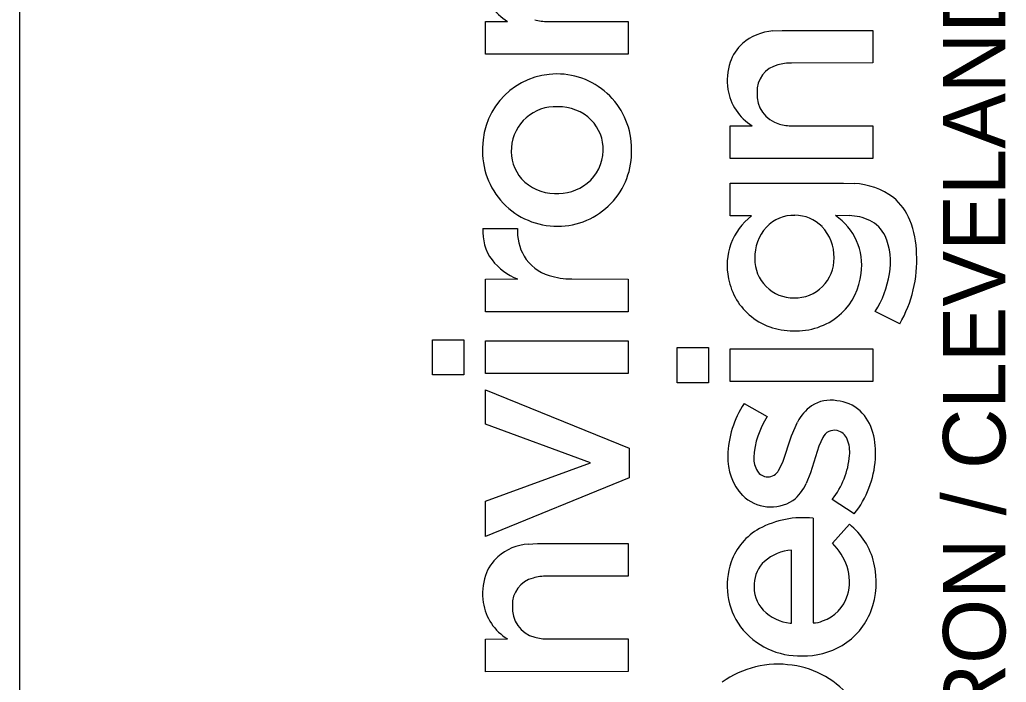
# Model space of a CAD drawing. Extents: x -0.2 to 34, y 0 to 22.
# Drawn here: x 32 to 32.901, y 2.778 to 3.382 of the extents above; entities that cross this region are included whole.
import ezdxf

# ---------------------------------------------------------------- set-up
doc = ezdxf.new("R2010")
doc.units = 0
doc.layers.add('SG_P_Poles', color=7, linetype='Continuous')
doc.layers.add('SH_Data', color=7, linetype='Continuous')

msp = doc.modelspace()

# ---------------------------------------------------------------- linework, layer by layer
at = {"layer": 'SG_P_Poles'}
msp.add_line((32, 0.5), (32, 21.5), dxfattribs=at)
at = {"layer": 'SH_Data'}
for p, q in [((32.42542, 3.38066), (32.44552, 3.38071)), ((32.42542, 3.35086), (32.42542, 3.38066)), ((32.48222, 3.38071), (32.55569, 3.38071)), ((32.55569, 3.38071), (32.55571, 3.35096)), ((32.68784, 3.3722), (32.69634, 3.37266)), ((32.69634, 3.37266), (32.77916, 3.37266)), ((32.77916, 3.37266), (32.77917, 3.34287)), ((32.55571, 3.35096), (32.42542, 3.35086)), ((32.77917, 3.34287), (32.70485, 3.3428)), ((32.64888, 3.2855), (32.66897, 3.28555)), ((32.64888, 3.25569), (32.64888, 3.2855)), ((32.70568, 3.28555), (32.77915, 3.28555)), ((32.77915, 3.28555), (32.77917, 3.25579)), ((32.77917, 3.25579), (32.64888, 3.25569)), ((32.6489, 3.20336), (32.64889, 3.23322)), ((32.64889, 3.23322), (32.75236, 3.23322)), ((32.75236, 3.23322), (32.76191, 3.23285)), ((32.66836, 3.20336), (32.6489, 3.20336)), ((32.75763, 3.20356), (32.74487, 3.20361)), ((32.42299, 3.19193), (32.45454, 3.19193)), ((32.42542, 3.14577), (32.45473, 3.14579)), ((32.42542, 3.11593), (32.42542, 3.14577)), ((32.50413, 3.14581), (32.55571, 3.14573)), ((32.55571, 3.14573), (32.55565, 3.11593)), ((32.55565, 3.11593), (32.42542, 3.11593)), ((32.8036, 3.10491), (32.7812, 3.11598)), ((32.37705, 3.05818), (32.37705, 3.09026)), ((32.37705, 3.09026), (32.40543, 3.09026)), ((32.40543, 3.09026), (32.40543, 3.05818)), ((32.42542, 3.05942), (32.42542, 3.08928)), ((32.42542, 3.08928), (32.55571, 3.08928)), ((32.55571, 3.08928), (32.55571, 3.05942)), ((32.60051, 3.05111), (32.60051, 3.08319)), ((32.60051, 3.08319), (32.62889, 3.08319)), ((32.62889, 3.08319), (32.62889, 3.05111)), ((32.64888, 3.05234), (32.64888, 3.0822)), ((32.64888, 3.0822), (32.77917, 3.0822)), ((32.77917, 3.0822), (32.77917, 3.05234)), ((32.40543, 3.05818), (32.37705, 3.05818)), ((32.55571, 3.05942), (32.42542, 3.05942)), ((32.62889, 3.05111), (32.60051, 3.05111)), ((32.77917, 3.05234), (32.64888, 3.05234)), ((32.42542, 3.01327), (32.42542, 3.0446)), ((32.42542, 3.0446), (32.5567, 2.9913)), ((32.66151, 3.03207), (32.68268, 3.02025)), ((32.52117, 2.97798), (32.42542, 3.01327)), ((32.70483, 3.00258), (32.71036, 3.01526)), ((32.69675, 2.97868), (32.70483, 3.00258)), ((32.73342, 3.00101), (32.72985, 2.9933)), ((32.5567, 2.9913), (32.5567, 2.96441)), ((32.72985, 2.9933), (32.72213, 2.96882)), ((32.42542, 2.94294), (32.52117, 2.97798)), ((32.69299, 2.97117), (32.69675, 2.97868)), ((32.5567, 2.96441), (32.42542, 2.91086)), ((32.72213, 2.96882), (32.71822, 2.95921)), ((32.42542, 2.91086), (32.42542, 2.94294)), ((32.76214, 2.93141), (32.74198, 2.94469)), ((32.72453, 2.92747), (32.72463, 2.83195)), ((32.74228, 2.90465), (32.75768, 2.922)), ((32.46439, 2.90397), (32.47289, 2.90443)), ((32.47289, 2.90443), (32.55571, 2.90443)), ((32.55571, 2.90443), (32.55571, 2.87465)), ((32.70489, 2.83182), (32.70489, 2.89834)), ((32.55571, 2.87465), (32.4814, 2.87457)), ((32.70361, 2.83165), (32.70489, 2.83182)), ((32.42542, 2.81728), (32.44552, 2.81733)), ((32.42542, 2.78747), (32.42542, 2.81728)), ((32.48222, 2.81733), (32.55569, 2.81733)), ((32.55569, 2.81733), (32.55571, 2.78756)), ((32.55571, 2.78756), (32.42542, 2.78747))]:
    msp.add_line(p, q, dxfattribs=at)
for points in [[(32.42542, 3.35086), (32.42542, 3.38066), (32.44552, 3.38071)], [(32.48222, 3.38071), (32.55569, 3.38071), (32.55571, 3.35096), (32.42542, 3.35086)], [(32.68784, 3.3722), (32.69634, 3.37266), (32.77916, 3.37266), (32.77917, 3.34287), (32.70485, 3.3428)], [(32.64888, 3.25569), (32.64888, 3.2855), (32.66897, 3.28555)], [(32.70568, 3.28555), (32.77915, 3.28555), (32.77917, 3.25579), (32.64888, 3.25569)], [(32.66836, 3.20336), (32.6489, 3.20336), (32.64889, 3.23322), (32.75236, 3.23322), (32.76191, 3.23285)], [(32.75763, 3.20356), (32.74487, 3.20361)], [(32.42299, 3.19193), (32.45454, 3.19193)], [(32.50413, 3.14581), (32.55571, 3.14573), (32.55565, 3.11593), (32.42542, 3.11593)], [(32.42542, 3.11593), (32.42542, 3.14577), (32.45473, 3.14579)], [(32.8036, 3.10491), (32.7812, 3.11598)], [(32.66151, 3.03207), (32.68268, 3.02025)], [(32.69299, 2.97117), (32.69675, 2.97868), (32.70483, 3.00258), (32.71036, 3.01526)], [(32.73342, 3.00101), (32.72985, 2.9933), (32.72213, 2.96882), (32.71822, 2.95921)], [(32.76214, 2.93141), (32.74198, 2.94469)], [(32.72453, 2.92747), (32.72463, 2.83195)], [(32.74228, 2.90465), (32.75768, 2.922)], [(32.46439, 2.90397), (32.47289, 2.90443), (32.55571, 2.90443), (32.55571, 2.87465), (32.4814, 2.87457)], [(32.70361, 2.83165), (32.70489, 2.83182), (32.70489, 2.89834)], [(32.42542, 2.78747), (32.42542, 2.81728), (32.44552, 2.81733)], [(32.48222, 2.81733), (32.55569, 2.81733), (32.55571, 2.78756), (32.42542, 2.78747)]]:
    msp.add_lwpolyline(points, dxfattribs=at)
for points in [[(32.37705, 3.05818), (32.37705, 3.09026), (32.40543, 3.09026), (32.40543, 3.05818)], [(32.42542, 3.05942), (32.42542, 3.08928), (32.55571, 3.08928), (32.55571, 3.05942)], [(32.60051, 3.05111), (32.60051, 3.08319), (32.62889, 3.08319), (32.62889, 3.05111)], [(32.64888, 3.05234), (32.64888, 3.0822), (32.77917, 3.0822), (32.77917, 3.05234)], [(32.42542, 2.91086), (32.42542, 2.94294), (32.52117, 2.97798), (32.42542, 3.01327), (32.42542, 3.0446), (32.5567, 2.9913), (32.5567, 2.96441)]]:
    msp.add_lwpolyline(points, close=True, dxfattribs=at)
for centre, radius, start, end in [((32.47027, 3.42141), 0.04763, 188.96462, 238.69865), ((32.47027, 3.42141), 0.04763, 188.96462, 238.69865), ((32.48183, 3.42286), 0.04215, 254.08913, 270.52838), ((32.48183, 3.42286), 0.04215, 254.08913, 270.52838), ((32.69216, 3.32251), 0.04988, 94.97056, 130.22484), ((32.69216, 3.32251), 0.04988, 94.97056, 130.22484), ((32.68694, 3.33085), 0.04016, 132.22383, 161.68229), ((32.68694, 3.33085), 0.04016, 132.22383, 161.68229), ((32.70217, 3.32642), 0.05602, 162.27398, 187.79173), ((32.70217, 3.32642), 0.05602, 162.27398, 187.79173), ((32.70453, 3.29679), 0.04601, 89.60515, 105.33026), ((32.70453, 3.29679), 0.04601, 89.60515, 105.33026), ((32.69828, 3.31689), 0.02498, 103.68683, 182.21395), ((32.69828, 3.31689), 0.02498, 103.68683, 182.21395), ((32.49014, 3.26543), 0.0674, 89.84756, 179.64047), ((32.49014, 3.26543), 0.0674, 89.84756, 179.64047), ((32.49057, 3.26474), 0.0681, 359.54009, 90.21138), ((32.49057, 3.26474), 0.0681, 359.54009, 90.21138), ((32.69372, 3.32624), 0.04763, 188.96462, 238.69865), ((32.69372, 3.32624), 0.04763, 188.96462, 238.69865), ((32.7008, 3.31381), 0.02757, 175.58441, 255.13816), ((32.7008, 3.31381), 0.02757, 175.58441, 255.13816), ((32.48923, 3.26263), 0.0404, 87.04809, 175.57259), ((32.48923, 3.26263), 0.0404, 87.04809, 175.57259), ((32.49204, 3.25999), 0.04299, 45.84264, 90.98008), ((32.49204, 3.25999), 0.04299, 45.84264, 90.98008), ((32.49458, 3.26421), 0.03821, 357.88569, 44.15902), ((32.49458, 3.26421), 0.03821, 357.88569, 44.15902), ((32.70529, 3.32769), 0.04215, 254.08913, 270.52838), ((32.70529, 3.32769), 0.04215, 254.08913, 270.52838), ((32.49083, 3.26209), 0.06819, 176.8344, 270.40384), ((32.49083, 3.26209), 0.06819, 176.8344, 270.40384), ((32.48729, 3.2625), 0.03848, 175.15378, 221.14706), ((32.48729, 3.2625), 0.03848, 175.15378, 221.14706), ((32.49123, 3.26139), 0.06749, 270.06243, 2.37759), ((32.49123, 3.26139), 0.06749, 270.06243, 2.37759), ((32.49446, 3.26318), 0.0383, 308.28936, 359.43468), ((32.49446, 3.26318), 0.0383, 308.28936, 359.43468), ((32.48919, 3.26607), 0.04228, 223.09994, 268.80895), ((32.48919, 3.26607), 0.04228, 223.09994, 268.80895), ((32.49096, 3.2679), 0.04418, 266.56515, 308.06078), ((32.49096, 3.2679), 0.04418, 266.56515, 308.06078), ((32.75907, 3.16789), 0.06503, 53.40344, 87.49062), ((32.75907, 3.16789), 0.06503, 53.40344, 87.49062), ((32.76517, 3.18039), 0.05141, 21.60748, 50.5577), ((32.76517, 3.18039), 0.05141, 21.60748, 50.5577), ((32.70292, 3.15813), 0.05692, 127.37482, 192.22468), ((32.70292, 3.15813), 0.05692, 127.37482, 192.22468), ((32.70693, 3.16927), 0.0346, 88.47302, 136.42562), ((32.70693, 3.16927), 0.0346, 88.47302, 136.42562), ((32.70814, 3.16963), 0.03424, 44.27195, 90.47623), ((32.70814, 3.16963), 0.03424, 44.27195, 90.47623), ((32.71421, 3.15829), 0.05472, 352.1125, 55.92295), ((32.71421, 3.15829), 0.05472, 352.1125, 55.92295), ((32.75666, 3.15725), 0.04633, 65.01687, 88.8011), ((32.75666, 3.15725), 0.04633, 65.01687, 88.8011), ((32.7626, 3.17155), 0.03085, 26.26808, 63.80301), ((32.7626, 3.17155), 0.03085, 26.26808, 63.80301), ((32.73069, 3.16714), 0.08835, 1.15143, 21.3627), ((32.73069, 3.16714), 0.08835, 1.15143, 21.3627), ((32.46616, 3.18882), 0.04329, 175.87313, 216.34747), ((32.46616, 3.18882), 0.04329, 175.87313, 216.34747), ((32.50087, 3.18948), 0.04639, 176.9688, 209.60636), ((32.50087, 3.18948), 0.04639, 176.9688, 209.60636), ((32.71141, 3.16602), 0.0401, 137.46739, 182.33237), ((32.71141, 3.16602), 0.0401, 137.46739, 182.33237), ((32.70368, 3.166), 0.03996, 358.57141, 43.53765), ((32.70368, 3.166), 0.03996, 358.57141, 43.53765), ((32.73565, 3.16154), 0.05953, 349.30734, 23.43071), ((32.73565, 3.16154), 0.05953, 349.30734, 23.43071), ((32.47466, 3.19716), 0.05511, 218.09809, 248.7907), ((32.47466, 3.19716), 0.05511, 218.09809, 248.7907), ((32.49514, 3.18814), 0.04079, 211.94466, 253.2028), ((32.49514, 3.18814), 0.04079, 211.94466, 253.2028), ((32.70645, 3.1637), 0.03511, 178.88208, 271.08374), ((32.70645, 3.1637), 0.03511, 178.88208, 271.08374), ((32.70818, 3.16404), 0.03546, 268.27882, 1.55016), ((32.70818, 3.16404), 0.03546, 268.27882, 1.55016), ((32.70538, 3.16244), 0.11383, 329.6388, 3.25998), ((32.70538, 3.16244), 0.11383, 329.6388, 3.25998), ((32.50465, 3.2165), 0.07069, 252.46555, 269.57296), ((32.50465, 3.2165), 0.07069, 252.46555, 269.57296), ((32.70463, 3.15696), 0.05837, 190.75182, 231.28919), ((32.70463, 3.15696), 0.05837, 190.75182, 231.28919), ((32.70988, 3.15708), 0.05887, 313.74196, 353.8554), ((32.70988, 3.15708), 0.05887, 313.74196, 353.8554), ((32.70738, 3.16334), 0.08771, 327.31495, 351.57478), ((32.70738, 3.16334), 0.08771, 327.31495, 351.57478), ((32.70632, 3.16112), 0.06269, 232.46061, 272.59022), ((32.70632, 3.16112), 0.06269, 232.46061, 272.59022), ((32.70954, 3.15901), 0.06051, 269.6361, 312.70877), ((32.70954, 3.15901), 0.06051, 269.6361, 312.70877), ((32.73636, 2.98258), 0.08973, 146.53104, 178.7571), ((32.73636, 2.98258), 0.08973, 146.53104, 178.7571), ((32.74661, 2.99713), 0.04053, 125.51182, 153.41595), ((32.74661, 2.99713), 0.04053, 125.51182, 153.41595), ((32.7406, 3.0026), 0.03263, 80.17192, 122.51969), ((32.7406, 3.0026), 0.03263, 80.17192, 122.51969), ((32.74278, 2.99824), 0.03667, 47.79344, 84.68918), ((32.74278, 2.99824), 0.03667, 47.79344, 84.68918), ((32.74519, 2.9789), 0.07495, 146.51121, 176.91007), ((32.74519, 2.9789), 0.07495, 146.51121, 176.91007), ((32.73788, 2.9946), 0.04267, 14.9966, 46.20632), ((32.73788, 2.9946), 0.04267, 14.9966, 46.20632), ((32.74384, 2.99631), 0.01143, 76.66094, 155.7053), ((32.74384, 2.99631), 0.01143, 76.66094, 155.7053), ((32.74397, 2.99511), 0.01256, 21.5098, 78.52618), ((32.74397, 2.99511), 0.01256, 21.5098, 78.52618), ((32.71044, 2.98674), 0.07121, 355.83062, 15.39138), ((32.71044, 2.98674), 0.07121, 355.83062, 15.39138), ((32.72592, 2.98766), 0.03209, 354.57264, 22.06805), ((32.72592, 2.98766), 0.03209, 354.57264, 22.06805), ((32.69666, 2.98238), 0.05005, 177.53659, 222.79318), ((32.69666, 2.98238), 0.05005, 177.53659, 222.79318), ((32.6931, 2.98233), 0.02276, 178.47474, 211.08679), ((32.6931, 2.98233), 0.02276, 178.47474, 211.08679), ((32.68248, 2.99149), 0.0757, 321.81101, 354.79685), ((32.68248, 2.99149), 0.0757, 321.81101, 354.79685), ((32.68952, 2.9882), 0.09219, 321.9777, 355.87384), ((32.68952, 2.9882), 0.09219, 321.9777, 355.87384), ((32.68331, 2.9767), 0.01148, 212.23676, 268.37769), ((32.68331, 2.9767), 0.01148, 212.23676, 268.37769), ((32.68342, 2.97589), 0.01067, 267.71603, 333.73375), ((32.68342, 2.97589), 0.01067, 267.71603, 333.73375), ((32.68098, 2.9758), 0.04077, 308.08772, 335.98736), ((32.68098, 2.9758), 0.04077, 308.08772, 335.98736), ((32.68599, 2.97535), 0.0375, 225.98539, 302.47965), ((32.68599, 2.97535), 0.0375, 225.98539, 302.47965), ((32.7152, 2.84414), 0.08384, 83.61499, 118.28755), ((32.7152, 2.84414), 0.08384, 83.61499, 118.28755), ((32.71744, 2.87167), 0.06443, 13.53365, 51.36148), ((32.71744, 2.87167), 0.06443, 13.53365, 51.36148), ((32.70239, 2.86906), 0.05583, 118.83082, 160.62438), ((32.70239, 2.86906), 0.05583, 118.83082, 160.62438), ((32.46871, 2.85428), 0.04988, 94.96958, 130.22249), ((32.46871, 2.85428), 0.04988, 94.96958, 130.22249), ((32.70378, 2.86556), 0.05486, 19.03571, 45.44059), ((32.70378, 2.86556), 0.05486, 19.03571, 45.44059), ((32.46348, 2.86263), 0.04015, 132.22192, 161.68183), ((32.46348, 2.86263), 0.04015, 132.22192, 161.68183), ((32.70785, 2.85609), 0.04235, 94.00805, 130.88169), ((32.70785, 2.85609), 0.04235, 94.00805, 130.88169), ((32.71041, 2.86612), 0.06437, 160.52012, 215.78311), ((32.71041, 2.86612), 0.06437, 160.52012, 215.78311), ((32.70048, 2.86628), 0.02985, 132.98507, 177.179), ((32.70048, 2.86628), 0.02985, 132.98507, 177.179), ((32.71069, 2.8697), 0.047, 344.60586, 17.007), ((32.71069, 2.8697), 0.047, 344.60586, 17.007), ((32.70635, 2.86921), 0.07579, 339.3542, 13.37853), ((32.70635, 2.86921), 0.07579, 339.3542, 13.37853), ((32.47872, 2.85819), 0.05601, 162.27355, 187.79185), ((32.47872, 2.85819), 0.05601, 162.27355, 187.79185), ((32.48108, 2.82856), 0.04601, 89.60494, 105.3284), ((32.48108, 2.82856), 0.04601, 89.60494, 105.3284), ((32.47482, 2.84867), 0.02498, 103.68646, 182.21874), ((32.47482, 2.84867), 0.02498, 103.68646, 182.21874), ((32.7017, 2.86503), 0.03115, 175.00126, 223.28301), ((32.7017, 2.86503), 0.03115, 175.00126, 223.28301), ((32.7224, 2.86715), 0.03504, 288.00773, 343.55078), ((32.7224, 2.86715), 0.03504, 288.00773, 343.55078), ((32.47026, 2.85802), 0.04762, 188.96199, 238.70369), ((32.47026, 2.85802), 0.04762, 188.96199, 238.70369), ((32.47735, 2.84558), 0.02756, 175.58538, 255.14386), ((32.47735, 2.84558), 0.02756, 175.58538, 255.14386), ((32.70891, 2.87363), 0.04231, 225.06188, 262.79738), ((32.70891, 2.87363), 0.04231, 225.06188, 262.79738), ((32.71894, 2.8652), 0.0626, 300.94269, 338.73225), ((32.71894, 2.8652), 0.0626, 300.94269, 338.73225), ((32.72474, 2.85216), 0.02021, 269.7003, 294.8711), ((32.72474, 2.85216), 0.02021, 269.7003, 294.8711), ((32.71253, 2.87054), 0.06872, 217.74516, 271.65431), ((32.71253, 2.87054), 0.06872, 217.74516, 271.65431), ((32.48183, 2.85948), 0.04215, 254.09162, 270.52835), ((32.48183, 2.85948), 0.04215, 254.09162, 270.52835), ((32.71549, 2.87241), 0.07056, 269.20477, 300.33412), ((32.71549, 2.87241), 0.07056, 269.20477, 300.33412), ((32.69229, 2.70792), 0.08641, 81.19402, 125.99844), ((32.69229, 2.70792), 0.08641, 81.19402, 125.99844), ((32.69458, 2.71132), 0.08272, 37.85208, 82.40204), ((32.69458, 2.71132), 0.08272, 37.85208, 82.40204)]:
    msp.add_arc(centre, radius, start, end, dxfattribs=at)

# ---------------------------------------------------------------- texts
msp.add_text('AKRON / CLEVELAND / COLUMBUS', height=0.056969, rotation=90, dxfattribs=at).set_placement((32.90012, 2.638))

doc.saveas('drawing.dxf')
